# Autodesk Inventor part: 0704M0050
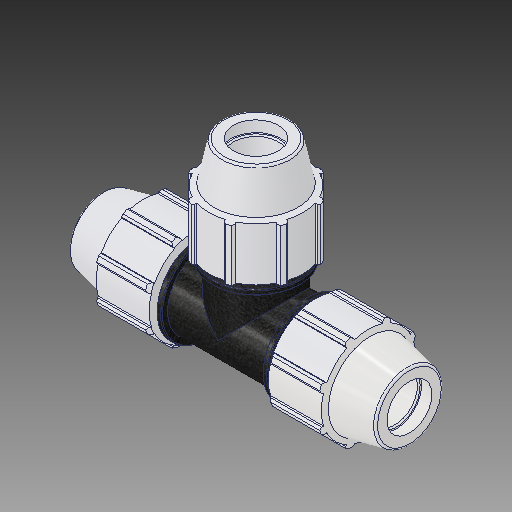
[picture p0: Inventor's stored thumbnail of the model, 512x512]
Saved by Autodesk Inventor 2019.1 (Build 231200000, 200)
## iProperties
Created: 2017-02
Part Number: 0704M0050
Material: PVC-Piping
Description: PLASSON TEE 1/2'' - 1/2'' - 1/2''
Document SubType Name: Modeling
Designer: KIM
Mass: 92.6774 g
Surface Area: 199.44 cm^2
Volume: 66.1981 cm^3
Density: 1.4 g/cm^3
Appearance: PTFE
Author: KIM
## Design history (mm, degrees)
derived "0704M0.ipt"
feature "Solid1::0704M0.ipt"
tag "TaggingFeature1"
body "Solid1"
other parameters: "d_" = 21.2, "E_" = 48.006, "A_" = 73.914, "l_" = 56.896, "H_" = 145.034, "d2" = 21.2, "d4" = 6.1595, "d5" = 18.4785, "d7" = 48.006, "d11" = 2.4638, "d13" = 120 deg, "d14" = 31.8, "d15" = 12 deg, "d16" = 41.76522, "d18" = 1.06, "d19" = 35 deg, "d20" = 17.5 deg, "d21" = 44.64558, "d23" = 0, "d25" = 360 deg, "d27" = 0.96012, "d33" = 0.424, "d42" = 25.8699, "d43" = 1.44018, "d46" = 0.636, "d63" = 56.896, "d67" = 36.0045, "d76" = 21.2, "d77" = 48.006, "d78" = 12 deg, "d79" = 73.914, "d80" = 120 deg, "d81" = 31.8, "d82" = 6.1595, "d85" = 36.0045, "d86" = 41.76522, "d87" = 2.4638, "d88" = 2.4638, "d89" = 18.4785, "d90" = 25.8699, "d96" = 8.21267, "d98" = 44.64558, "d99" = 35 deg, "d100" = 17.5 deg, "d102" = 0, "d103" = 0.96012, "d107" = 360 deg, "d109" = 0.636, "d112" = 1.06, "d118" = 360 deg, "d121" = 0, "d128" = 145.034, "d131" = 19.08, "d132" = 19.08, "d133" = 56.896, "d134" = 1.13792, "d135" = 8.21267, "d152" = 0, "d154" = 0, "d156" = 0, "d158" = 0
